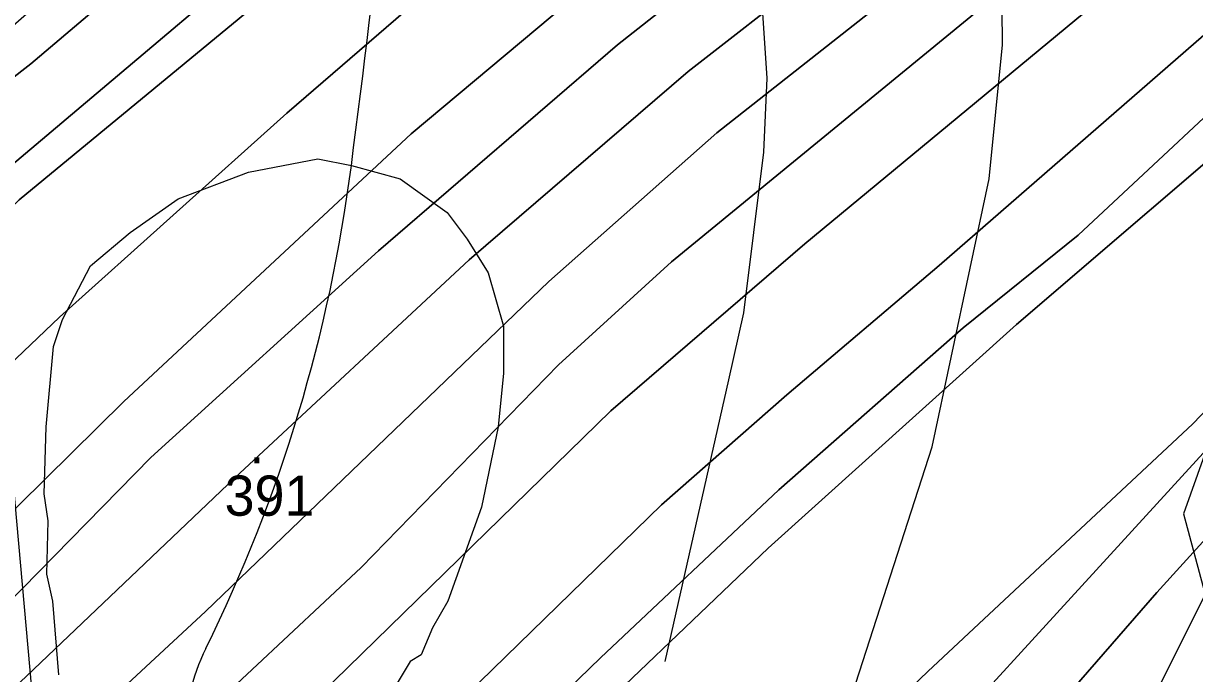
# Model space of a CAD drawing. Extents: x -510989 to -501240, y -1184665 to -1176098.
# Drawn here: x -504226.5 to -504051.9, y -1181563.8 to -1181466.8 of the extents above; entities that cross this region are included whole.
import ezdxf

# ---------------------------------------------------------------- set-up
doc = ezdxf.new("R2010")
doc.units = 0
for name, color, linetype in [('NAVRH_interakcni_prvky', 7, 'Continuous'), ('orna_puda', 7, 'Continuous'), ('ostatni_plocha_x_silnice', 7, 'Continuous'), ('STAV_povodi', 7, 'Continuous'), ('STAV_zaplavove_uzemi', 7, 'Continuous'), ('trvaly_travni_porost', 7, 'Continuous'), ('vrstevnice_01', 7, 'Continuous'), ('vrstevnice_02', 7, 'Continuous'), ('vrstevnice_03', 7, 'Continuous'), ('vrstevnice_05', 7, 'Continuous')]:
    doc.layers.add(name, color=color, linetype=linetype)

msp = doc.modelspace()

# ---------------------------------------------------------------- linework, layer by layer
at = {"layer": 'NAVRH_interakcni_prvky'}
msp.add_lwpolyline([(-504180.72, -1181675.18), (-504224.4, -1181575.54), (-504238.64, -1181416.52), (-504212.53, -1181295.47), (-504146.08, -1181212.4), (-504053.51, -1181124.58)], dxfattribs=at)
at = {"layer": 'orna_puda'}
for points in [[(-504036.26, -1181341.11), (-504096.44, -1181384.65), (-504154.15, -1181432.9), (-504227.12, -1181493.15), (-504304.33, -1181567.44), (-504325.51, -1181586.47), (-504359.83, -1181614.36), (-504368.28, -1181620.18), (-504370.38, -1181615.49), (-504353.81, -1181603.05), (-504337.64, -1181590.56), (-504315.67, -1181571.6), (-504288.62, -1181546.13), (-504230.73, -1181489.99), (-504175.46, -1181443.32), (-504111.85, -1181390.71), (-504093.27, -1181376.13), (-504073.12, -1181361.78), (-504017.65, -1181321.72)], [(-504047.1, -1181384.76), (-504121.78, -1181443.96), (-504168.7, -1181483.28), (-504211.54, -1181523.2), (-504254.5, -1181565.62), (-504289.52, -1181597.05), (-504301.27, -1181604.79), (-504318.48, -1181618.41), (-504338.99, -1181632.23), (-504356.12, -1181647.35), (-504361.76, -1181634.74), (-504328.96, -1181609.46), (-504311.79, -1181596), (-504278.03, -1181564.9), (-504221.1, -1181510.64), (-504187.21, -1181480.2), (-504140.99, -1181440.26), (-504079.21, -1181389.26), (-504051.54, -1181368.52)], [(-504049.09, -1181398.26), (-504077.92, -1181420.42), (-504112.69, -1181450.12), (-504137.91, -1181470.01), (-504173.54, -1181500.72), (-504207.48, -1181531.56), (-504245.87, -1181570.69), (-504290.31, -1181611.06), (-504315.13, -1181632.29), (-504350.91, -1181658.99), (-504356.12, -1181647.35), (-504338.99, -1181632.23), (-504318.48, -1181618.41), (-504301.27, -1181604.79), (-504289.52, -1181597.05), (-504254.5, -1181565.62), (-504211.54, -1181523.2), (-504168.7, -1181483.28), (-504121.78, -1181443.96), (-504047.1, -1181384.76)], [(-504030.95, -1181451.5), (-504089.97, -1181502.91), (-504112.64, -1181522.2), (-504131.34, -1181538.65), (-504173.95, -1181580.18), (-504188.24, -1181593.72), (-504215.6, -1181621.07), (-504224.49, -1181628.89), (-504236.46, -1181638.44), (-504292.38, -1181685.95), (-504327.46, -1181711.39), (-504329.5, -1181706.83), (-504333.77, -1181697.3), (-504318.39, -1181686.88), (-504286.11, -1181662.28), (-504255.3, -1181636.01), (-504220.42, -1181604.9), (-504200.79, -1181585.03), (-504138.91, -1181524.63), (-504109.96, -1181499.71), (-503999.82, -1181408.51)], [(-504175.46, -1181443.32), (-504230.73, -1181489.99), (-504288.62, -1181546.13), (-504315.67, -1181571.6), (-504337.64, -1181590.56), (-504353.81, -1181603.05), (-504370.38, -1181615.49), (-504372.64, -1181610.45), (-504374.83, -1181605.56), (-504367.79, -1181601.05), (-504323.53, -1181564.59), (-504298.04, -1181540.63), (-504286.63, -1181529.44), (-504258.17, -1181502.98), (-504235.12, -1181480.4), (-504225.38, -1181472.86), (-504164.5, -1181421.18)], [(-504038.56, -1181469.74), (-504069.23, -1181498.4), (-504086.37, -1181512.24), (-504113.88, -1181536.39), (-504140.47, -1181561.44), (-504166.38, -1181586.63), (-504167.15, -1181587.38), (-504172.49, -1181592.58), (-504188.89, -1181609.11), (-504211.38, -1181629.97), (-504251.27, -1181664.55), (-504281.68, -1181689.3), (-504323.53, -1181720.17), (-504327.46, -1181711.39), (-504292.38, -1181685.95), (-504236.46, -1181638.44), (-504224.49, -1181628.89), (-504215.6, -1181621.07), (-504188.24, -1181593.72), (-504173.95, -1181580.18), (-504131.34, -1181538.65), (-504112.64, -1181522.2), (-504089.97, -1181502.91), (-504030.95, -1181451.5)], [(-504323.53, -1181720.17), (-504281.68, -1181689.3), (-504251.27, -1181664.55), (-504211.38, -1181629.97), (-504188.89, -1181609.11), (-504172.49, -1181592.58), (-504167.15, -1181587.38), (-504166.38, -1181586.63), (-504140.47, -1181561.44), (-504113.88, -1181536.39), (-504086.37, -1181512.24), (-504069.23, -1181498.4), (-504038.56, -1181469.74)], [(-504038.49, -1181477.53), (-504078.43, -1181511.72), (-504115.44, -1181545.08), (-504148.12, -1181576.34), (-504159.86, -1181587.97), (-504162.53, -1181590.62), (-504177.73, -1181605.67), (-504206.72, -1181632.65), (-504222.74, -1181646.59), (-504250.04, -1181669.72), (-504279.32, -1181694.3), (-504299.88, -1181709.69)], [(-504018.64, -1181495.97), (-504140.54, -1181629.34), (-504152.37, -1181642.32), (-504167.84, -1181662.04), (-504175.88, -1181672.87), (-504183.71, -1181685.06), (-504216.22, -1181746.78), (-504228.1, -1181760.35), (-504239.53, -1181770.63), (-504251.27, -1181778.05), (-504269.64, -1181785.34), (-504292.73, -1181787.64), (-504293.36, -1181787.59), (-504309.83, -1181750.79), (-504251.71, -1181707.68), (-504209.06, -1181675), (-504185.42, -1181656.07), (-504155.8, -1181627.38), (-504137.42, -1181607.75), (-504124.83, -1181595.32), (-504091.63, -1181563.5), (-504052.11, -1181526.57), (-504020.49, -1181493.63)]]:
    msp.add_lwpolyline(points, dxfattribs=at)
for points in [[(-503944.07, -1181330.17), (-503962.31, -1181344.77), (-504064.91, -1181423.18), (-504109.25, -1181459.83), (-504127.4, -1181473.98), (-504160.04, -1181502.09), (-504194.96, -1181534.62), (-504260.14, -1181596.6), (-504303.09, -1181634.43), (-504336.37, -1181660.22), (-504347.05, -1181667.61), (-504350.91, -1181658.99), (-504315.13, -1181632.29), (-504290.31, -1181611.06), (-504245.87, -1181570.69), (-504207.48, -1181531.56), (-504173.54, -1181500.72), (-504137.91, -1181470.01), (-504112.69, -1181450.12), (-504077.92, -1181420.42), (-504049.09, -1181398.26), (-503995.76, -1181359.87), (-503976.68, -1181345.32), (-503948.03, -1181322.12)], [(-503942.1, -1181334.17), (-503939.89, -1181338.66), (-503941.64, -1181340.1), (-504036.16, -1181414.61), (-504123.08, -1181483.11), (-504148.17, -1181505.32), (-504199.33, -1181554.54), (-504223.99, -1181577.43), (-504255.31, -1181605.86), (-504302.39, -1181646.52), (-504333.53, -1181670.75), (-504342.67, -1181677.41), (-504344.68, -1181672.91), (-504347.05, -1181667.61), (-504336.37, -1181660.22), (-504303.09, -1181634.43), (-504260.14, -1181596.6), (-504194.96, -1181534.62), (-504160.04, -1181502.09), (-504127.4, -1181473.98), (-504109.25, -1181459.83), (-504064.91, -1181423.18), (-503962.31, -1181344.77), (-503944.07, -1181330.17)], [(-503939.89, -1181338.66), (-503936.34, -1181345.88), (-503944.63, -1181352.64), (-504023.33, -1181415.35), (-504054.92, -1181440.88), (-504129.87, -1181502.39), (-504146.7, -1181517.74), (-504176.13, -1181548), (-504219.49, -1181588.54), (-504245.7, -1181612.57), (-504295.39, -1181654.87), (-504302.39, -1181646.52), (-504255.31, -1181605.86), (-504223.99, -1181577.43), (-504199.33, -1181554.54), (-504148.17, -1181505.32), (-504123.08, -1181483.11), (-504036.16, -1181414.61), (-503941.64, -1181340.1)], [(-504036.26, -1181341.11), (-504026.59, -1181350.42), (-504051.54, -1181368.52), (-504079.21, -1181389.26), (-504140.99, -1181440.26), (-504187.21, -1181480.2), (-504221.1, -1181510.64), (-504278.03, -1181564.9), (-504311.79, -1181596), (-504328.96, -1181609.46), (-504361.76, -1181634.74), (-504368.28, -1181620.18), (-504359.83, -1181614.36), (-504325.51, -1181586.47), (-504304.33, -1181567.44), (-504227.12, -1181493.15), (-504154.15, -1181432.9), (-504096.44, -1181384.65)], [(-503944.63, -1181352.64), (-503936.34, -1181345.88), (-503932.23, -1181354.23), (-503999.82, -1181408.51), (-504109.96, -1181499.71), (-504138.91, -1181524.63), (-504200.79, -1181585.03), (-504220.42, -1181604.9), (-504255.3, -1181636.01), (-504286.11, -1181662.28), (-504318.39, -1181686.88), (-504333.77, -1181697.3), (-504338.44, -1181686.86), (-504295.39, -1181654.87), (-504245.7, -1181612.57), (-504219.49, -1181588.54), (-504176.13, -1181548), (-504146.7, -1181517.74), (-504129.87, -1181502.39), (-504054.92, -1181440.88), (-504023.33, -1181415.35)], [(-504038.49, -1181477.53), (-504020.49, -1181493.63), (-504052.11, -1181526.57), (-504091.63, -1181563.5), (-504124.83, -1181595.32), (-504137.42, -1181607.75), (-504155.8, -1181627.38), (-504185.42, -1181656.07), (-504209.06, -1181675), (-504251.71, -1181707.68), (-504309.83, -1181750.79), (-504321.41, -1181724.92), (-504299.88, -1181709.69), (-504279.32, -1181694.3), (-504250.04, -1181669.72), (-504222.74, -1181646.59), (-504206.72, -1181632.65), (-504177.73, -1181605.67), (-504162.53, -1181590.62), (-504159.86, -1181587.97), (-504148.12, -1181576.34), (-504115.44, -1181545.08), (-504078.43, -1181511.72)]]:
    msp.add_lwpolyline(points, close=True, dxfattribs=at)
at = {"layer": 'ostatni_plocha_x_silnice'}
for points in [[(-503984.82, -1181471.63), (-504057.5, -1181551.71), (-504082.51, -1181580.45), (-504085.43, -1181583.39), (-504091.66, -1181589.66), (-504120.67, -1181618.87), (-504129.43, -1181627.99), (-504146.11, -1181647.87), (-504156.06, -1181660.28), (-504161.3, -1181666.82), (-504167.62, -1181675.86), (-504168.69, -1181677.39), (-504172.89, -1181683.82), (-504201.19, -1181738.23)], [(-504216.22, -1181746.78), (-504183.71, -1181685.06), (-504175.88, -1181672.87), (-504167.84, -1181662.04), (-504152.37, -1181642.32), (-504140.54, -1181629.34), (-504018.64, -1181495.97)]]:
    msp.add_lwpolyline(points, dxfattribs=at)
at = {"layer": 'STAV_povodi'}
for centre, radius, start, end in [((-507374.38, -1181076.27), 3223.19, 352.66102, 355.7168), ((-504405.67, -1181458.63), 229.96, 333.8243, 352.661), ((-504170.26, -1181574.34), 32.35, 153.8243, 204.0059)]:
    msp.add_arc(centre, radius, start, end, dxfattribs=at)
at = {"layer": 'STAV_zaplavove_uzemi'}
for points in [[(-504594.17, -1181642.09), (-504629.77, -1181535.28), (-504650.39, -1181443.46), (-504674.75, -1181355.39), (-504706.6, -1181265.44), (-504719.72, -1181182.99), (-504747.83, -1181113.66), (-504727.29, -1181064.42), (-504683.65, -1181020.77), (-504624.52, -1180967.28), (-504575.24, -1180927.85), (-504544.27, -1180915.18), (-504445.72, -1180881.39), (-504404.89, -1180867.31), (-504292.26, -1180829.3), (-504179.63, -1180791.29), (-504099.38, -1180734.98), (-504020.54, -1180698.37), (-503957.18, -1180675.84), (-503893.83, -1180664.58), (-503865.67, -1180678.66), (-503817.8, -1180689.92), (-503788.24, -1180689.92), (-503764.3, -1180695.55), (-503736.15, -1180687.11), (-503717.85, -1180698.37), (-503716.44, -1180708.23)], [(-502250.32, -1184002.61), (-502355.07, -1183875.41), (-502442.37, -1183790.61), (-502477.29, -1183700.82), (-502532.16, -1183578.61), (-502567.08, -1183448.91), (-502626.05, -1183402.34), (-502705.41, -1183380.59), (-502814.2, -1183349.87), (-502882.03, -1183297.39), (-502931.95, -1183237.24), (-503042.02, -1183107.97), (-503139.64, -1183018.94), (-503222.14, -1182957.59), (-503308.56, -1182839.96), (-503316.24, -1182784.92), (-503330.32, -1182756.77), (-503348.24, -1182719.65), (-503334.16, -1182651.82), (-503323.92, -1182595.5), (-503313.68, -1182526.39), (-503294.1, -1182480.5), (-503251.86, -1182396.03), (-503229.34, -1182314.37), (-503216.1, -1182227.15), (-503242.43, -1182174.5), (-503271.86, -1182129.59), (-503287.34, -1182081.58), (-503343.88, -1182028.1), (-503361.79, -1182008.91), (-503396.35, -1181952.59), (-503442.43, -1181933.39), (-503497.46, -1181888.6), (-503525.62, -1181860.44), (-503528.18, -1181837.4), (-503548.66, -1181767.01), (-503558.9, -1181729.89), (-503576.82, -1181682.53), (-503578.1, -1181621.1), (-503567.86, -1181572.46), (-503552.5, -1181536.63), (-503538.04, -1181458.36), (-503518.33, -1181411.9), (-503509.88, -1181341.51), (-503497.21, -1181207.63), (-503499.77, -1181097.56), (-503498.02, -1181031.35), (-503510.82, -1180970.85), (-503549.22, -1180952.23), (-503571.32, -1180940.6), (-503605.07, -1180937.11), (-503651.61, -1180939.44), (-503671.39, -1180917.33), (-503679.53, -1180892.89), (-503713.27, -1180871.95), (-503727.24, -1180859.15), (-503734.22, -1180833.55), (-503728.4, -1180799.81), (-503741.2, -1180770.72), (-503722.82, -1180725.17), (-503721.54, -1180703.41), (-503731.78, -1180697.01), (-503767.61, -1180699.57), (-503790.65, -1180697.01), (-503817.53, -1180697.01), (-503861.04, -1180686.77), (-503889.2, -1180675.25), (-503900.72, -1180668.85), (-503953.2, -1180679.09), (-503997.99, -1180697.01), (-504063.27, -1180722.61), (-504109.34, -1180749.49), (-504142.62, -1180776.36), (-504177.18, -1180796.84), (-504211.73, -1180817.32), (-504414.98, -1180961.5), (-504472.7, -1180998.11), (-504544.51, -1181068.5), (-504600.82, -1181143.12), (-504621.94, -1181196.62), (-504641.65, -1181267.01), (-504660.25, -1181350.62), (-504634.7, -1181398.32), (-504617.66, -1181447.72), (-504600.62, -1181492.01), (-504587, -1181548.23), (-504592.11, -1181628.29), (-504569.96, -1181682.81), (-504568.26, -1181664.07), (-504554.63, -1181621.48), (-504547.82, -1181597.63)]]:
    msp.add_spline(points, degree=3, dxfattribs=at)
at = {"layer": 'trvaly_travni_porost'}
for points in [[(-504018.64, -1181309.98), (-504068.78, -1181345.73), (-504103.51, -1181372.38), (-504138.76, -1181400.31), (-504164.5, -1181421.18), (-504225.38, -1181472.86), (-504235.12, -1181480.4), (-504258.17, -1181502.98), (-504286.63, -1181529.44), (-504298.04, -1181540.63), (-504323.53, -1181564.59), (-504367.79, -1181601.05), (-504374.83, -1181605.56), (-504377.18, -1181600.3), (-504359.98, -1181587.77), (-504326.71, -1181559.76), (-504269.99, -1181506.44), (-504244.12, -1181481.44), (-504233.31, -1181471.69), (-504195.59, -1181438.64), (-504107.01, -1181367.8), (-504070.29, -1181339.68), (-504027.29, -1181308.5)], [(-504050.59, -1181575.1), (-504057.72, -1181585.95), (-504064.36, -1181596.35), (-504070.27, -1181605.94), (-504089.92, -1181660.22), (-504093.11, -1181669.4), (-504092.48, -1181659.16), (-504091.39, -1181633.16), (-504089.14, -1181615.28), (-504085.43, -1181583.39), (-504082.51, -1181580.45), (-504057.5, -1181551.71), (-503984.82, -1181471.63)]]:
    msp.add_lwpolyline(points, dxfattribs=at)
at = {"layer": 'vrstevnice_01'}
for points in [[(-504221.19, -1181564), (-504222.09, -1181553), (-504223, -1181549), (-504222.81, -1181541), (-504223.41, -1181537), (-504223.09, -1181527), (-504222, -1181515), (-504220.69, -1181511), (-504216.5, -1181503), (-504210.59, -1181498), (-504203.41, -1181493), (-504192.91, -1181489), (-504182.59, -1181487), (-504177.59, -1181488), (-504170.31, -1181490), (-504163.31, -1181495)], [(-504163.31, -1181495), (-504160.31, -1181499), (-504157.19, -1181504), (-504154.91, -1181512), (-504154.91, -1181519), (-504155.69, -1181527), (-504158.19, -1181539), (-504163.19, -1181553), (-504165.5, -1181557), (-504167.19, -1181561), (-504168.81, -1181562), (-504171.19, -1181566)], [(-504041.81, -1181507), (-504053.5, -1181540), (-504050.31, -1181552), (-504056.81, -1181565), (-504061.31, -1181579), (-504063.09, -1181606), (-504054.69, -1181652), (-504054.19, -1181667), (-504056.81, -1181698), (-504054.91, -1181709), (-504051.31, -1181718)]]:
    msp.add_lwpolyline(points, dxfattribs=at)
at = {"layer": 'vrstevnice_02'}
msp.add_lwpolyline([(-504049.41, -1181764), (-504058.41, -1181754), (-504066.91, -1181747), (-504075.91, -1181736), (-504078, -1181732), (-504081.5, -1181719), (-504083.59, -1181707), (-504084.19, -1181692), (-504089.09, -1181666), (-504101.59, -1181635), (-504104.59, -1181623), (-504103.31, -1181608), (-504100.91, -1181601), (-504101.5, -1181599), (-504107, -1181592), (-504109.19, -1181588), (-504106.5, -1181578), (-504091, -1181530), (-504082.5, -1181490), (-504080.5, -1181470), (-504080.65, -1181453.59)], dxfattribs=at)
at = {"layer": 'vrstevnice_03'}
msp.add_lwpolyline([(-504130.81, -1181562), (-504121.31, -1181520), (-504119.09, -1181510), (-504116.09, -1181486), (-504115.59, -1181475), (-504117.23, -1181450.29)], dxfattribs=at)

# ---------------------------------------------------------------- texts
at = {"layer": 'vrstevnice_05'}
for s, p in [('.', (-504192.82, -1181532.46)), ('391', (-504196.5, -1181540.26))]:
    msp.add_text(s, height=6, dxfattribs=at).set_placement(p)

doc.saveas('drawing.dxf')
